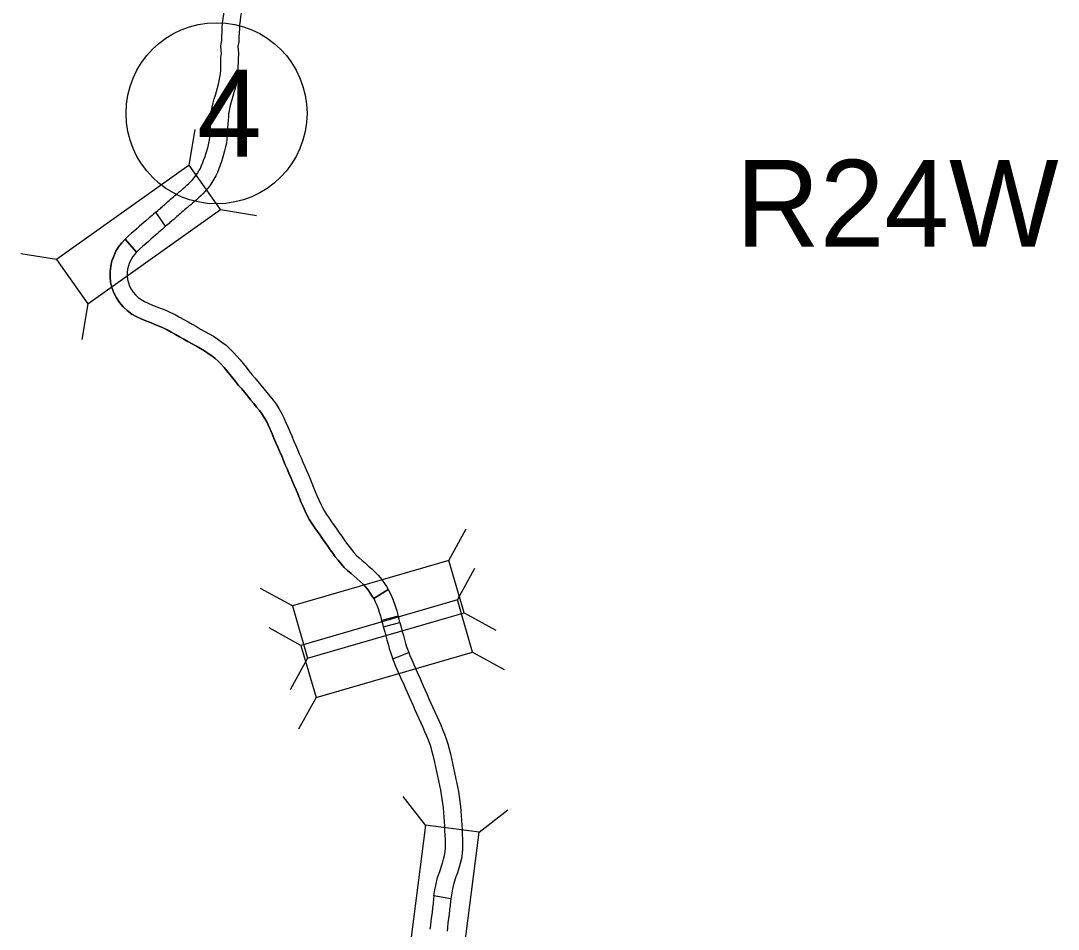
# Model space of a CAD drawing. Extents: x 77230 to 630905, y 790554 to 1662844.
# Drawn here: x 424792 to 439922, y 1490722 to 1503964 of the extents above; entities that cross this region are included whole.
import ezdxf

# ---------------------------------------------------------------- set-up
doc = ezdxf.new("R2010")
doc.units = 0
for name, color, linetype in [('Level 10', 7, 'Continuous'), ('Level 19', 7, 'Continuous'), ('Level 28', 7, 'Continuous'), ('Level 33', 7, 'Continuous')]:
    doc.layers.add(name, color=color, linetype=linetype)

msp = doc.modelspace()

# ---------------------------------------------------------------- linework, layer by layer
at = {"layer": 'Level 10'}
for points in [[(427712, 1503430), (427717, 1503485), (427714, 1503526), (427708, 1503599), (427723, 1503681), (427724, 1503736), (427727, 1503800), (427730, 1503861), (427734, 1503927), (427743, 1503997), (427751, 1504060), (427763, 1504127), (427776, 1504192), (427790, 1504255), (427804, 1504314), (427815, 1504372), (427825, 1504430), (427832, 1504483), (427834, 1504537), (427833, 1504598), (427822, 1504756), (428072, 1504757)], [(428072, 1504757), (428083, 1504600), (428084, 1504533), (428081, 1504461), (428072, 1504393), (428061, 1504328), (428048, 1504262), (428034, 1504199), (428020, 1504139), (428008, 1504081), (427998, 1504023), (427991, 1503966), (427983, 1503904), (427980, 1503849), (427977, 1503788), (427974, 1503726), (427972, 1503656), (427960, 1503588), (427964, 1503546), (427968, 1503483), (427961, 1503408)], [(428072, 1504757), (428083, 1504600), (428084, 1504533), (428081, 1504461), (428072, 1504393), (428061, 1504328), (428048, 1504262), (428034, 1504199), (428020, 1504139), (428008, 1504081), (427998, 1504023), (427991, 1503966), (427983, 1503904), (427980, 1503849), (427977, 1503788), (427974, 1503726), (427972, 1503656), (427960, 1503588), (427964, 1503546), (427968, 1503483), (427961, 1503408)], [(426905, 1500969), (426760, 1501173), (426791, 1501200), (426805, 1501212), (426819, 1501224), (426833, 1501235), (426846, 1501246), (426859, 1501258), (426872, 1501270), (426887, 1501283), (426904, 1501298), (426921, 1501313), (426938, 1501328), (426957, 1501345), (426976, 1501362), (426997, 1501379), (427018, 1501397), (427039, 1501416), (427062, 1501434), (427085, 1501453), (427109, 1501474), (427134, 1501495), (427160, 1501518), (427188, 1501542), (427216, 1501567), (427244, 1501593), (427271, 1501619), (427298, 1501647), (427323, 1501676), (427347, 1501708), (427370, 1501741), (427391, 1501775), (427411, 1501813), (427430, 1501855), (427448, 1501897), (427464, 1501941), (427480, 1501988), (427495, 1502037), (427510, 1502085), (427523, 1502132), (427534, 1502178), (427543, 1502224), (427550, 1502269), (427553, 1502314), (427557, 1502365), (427560, 1502417), (427563, 1502470), (427566, 1502525), (427570, 1502578), (427571, 1502637), (427585, 1502707), (427599, 1502768), (427614, 1502826), (427630, 1502881), (427645, 1502934), (427661, 1502988), (427675, 1503039), (427687, 1503088), (427696, 1503141), (427703, 1503192), (427708, 1503243), (427709, 1503298), (427711, 1503360), (427712, 1503430)], [(427961, 1503408), (427961, 1503354), (427959, 1503291), (427957, 1503229), (427952, 1503163), (427943, 1503102), (427932, 1503038), (427917, 1502976), (427901, 1502919), (427885, 1502865), (427870, 1502812), (427855, 1502761), (427842, 1502709), (427829, 1502654), (427820, 1502610), (427820, 1502567), (427815, 1502509), (427813, 1502456), (427809, 1502402), (427806, 1502349), (427803, 1502295), (427798, 1502240), (427790, 1502182), (427779, 1502125), (427765, 1502069), (427750, 1502015), (427734, 1501962), (427717, 1501911), (427700, 1501858), (427680, 1501805), (427659, 1501753), (427635, 1501703), (427610, 1501653), (427580, 1501605), (427549, 1501559), (427516, 1501517), (427482, 1501479), (427449, 1501444), (427416, 1501411), (427384, 1501382), (427353, 1501354), (427324, 1501329), (427297, 1501305), (427270, 1501283), (427245, 1501262), (427222, 1501243), (427200, 1501224), (427180, 1501207), (427160, 1501190), (427140, 1501173), (427122, 1501157), (427104, 1501141), (427086, 1501126), (427070, 1501111), (427054, 1501097), (427038, 1501082), (427023, 1501069), (427009, 1501057), (426995, 1501046), (426982, 1501034), (426968, 1501022), (426954, 1501010), (426939, 1500997), (426905, 1500969)], [(427961, 1503408), (427961, 1503354), (427959, 1503291), (427957, 1503229), (427952, 1503163), (427943, 1503102), (427932, 1503038), (427917, 1502976), (427901, 1502919), (427885, 1502865), (427870, 1502812), (427855, 1502761), (427842, 1502709), (427829, 1502654), (427820, 1502610), (427820, 1502567), (427815, 1502509), (427813, 1502456), (427809, 1502402), (427806, 1502349), (427803, 1502295), (427798, 1502240), (427790, 1502182), (427779, 1502125), (427765, 1502069), (427750, 1502015), (427734, 1501962), (427717, 1501911), (427700, 1501858), (427680, 1501805), (427659, 1501753), (427635, 1501703), (427610, 1501653), (427580, 1501605), (427549, 1501559), (427516, 1501517), (427482, 1501479), (427449, 1501444), (427416, 1501411), (427384, 1501382), (427353, 1501354), (427324, 1501329), (427297, 1501305), (427270, 1501283), (427245, 1501262), (427222, 1501243), (427200, 1501224), (427180, 1501207), (427160, 1501190), (427140, 1501173), (427122, 1501157), (427104, 1501141), (427086, 1501126), (427070, 1501111), (427054, 1501097), (427038, 1501082), (427023, 1501069), (427009, 1501057), (426995, 1501046), (426982, 1501034), (426968, 1501022), (426954, 1501010), (426939, 1500997), (426905, 1500969)], [(426760, 1501173), (426727, 1501144), (426708, 1501128), (426688, 1501110), (426666, 1501091), (426617, 1501049), (426588, 1501024), (426524, 1500968), (426488, 1500937), (426449, 1500903), (426407, 1500866), (426363, 1500827), (426314, 1500782)], [(426905, 1500969), (426852, 1500922), (426830, 1500902), (426806, 1500881), (426779, 1500859), (426751, 1500835), (426721, 1500809), (426688, 1500780), (426653, 1500749), (426614, 1500714), (426573, 1500679), (426530, 1500641), (426478, 1500593)], [(426478, 1500593), (426314, 1500782), (426265, 1500729), (426219, 1500669), (426180, 1500604), (426147, 1500535), (426122, 1500463), (426104, 1500387), (426095, 1500309), (426094, 1500230), (426103, 1500152), (426121, 1500074), (426149, 1499997), (426187, 1499924), (426232, 1499857), (426286, 1499794), (426345, 1499741), (426410, 1499689), (426483, 1499650), (426550, 1499618), (426617, 1499590), (426683, 1499564), (426749, 1499538)], [(426749, 1499538), (426683, 1499564), (426617, 1499590), (426550, 1499618), (426483, 1499650), (426410, 1499689), (426345, 1499741), (426286, 1499794), (426232, 1499857), (426187, 1499924), (426149, 1499997), (426121, 1500074), (426103, 1500152), (426094, 1500230), (426095, 1500309), (426104, 1500387), (426122, 1500463), (426147, 1500535), (426180, 1500604), (426219, 1500669), (426265, 1500729), (426314, 1500782), (426478, 1500593)], [(426478, 1500593), (426426, 1500528), (426401, 1500486), (426379, 1500440), (426362, 1500392), (426351, 1500343), (426345, 1500294), (426344, 1500244), (426350, 1500194), (426361, 1500144), (426378, 1500097), (426402, 1500052), (426431, 1500009), (426465, 1499969), (426506, 1499932), (426548, 1499899), (426596, 1499873), (426652, 1499846), (426712, 1499821), (426774, 1499796), (426839, 1499772)], [(426478, 1500593), (426426, 1500528), (426401, 1500486), (426379, 1500440), (426362, 1500392), (426351, 1500343), (426345, 1500294), (426344, 1500244), (426350, 1500194), (426361, 1500144), (426378, 1500097), (426402, 1500052), (426431, 1500009), (426465, 1499969), (426506, 1499932), (426548, 1499899), (426596, 1499873), (426652, 1499846), (426712, 1499821), (426774, 1499796), (426839, 1499772)], [(426839, 1499772), (426907, 1499745), (426976, 1499714), (427043, 1499681), (427108, 1499646), (427170, 1499611), (427232, 1499576), (427294, 1499541), (427354, 1499506), (427415, 1499471), (427476, 1499437), (427538, 1499402), (427601, 1499365), (427664, 1499325), (427726, 1499281), (427787, 1499234), (427843, 1499183), (427896, 1499129), (427945, 1499076), (427992, 1499021), (428035, 1498966), (428078, 1498914), (428120, 1498860), (428161, 1498809), (428204, 1498759), (428250, 1498705), (428295, 1498651), (428338, 1498597), (428381, 1498545), (428425, 1498491), (428471, 1498436), (428515, 1498376), (428557, 1498312), (428594, 1498246), (428628, 1498178), (428658, 1498109), (428687, 1498043), (428715, 1497977), (428743, 1497912), (428771, 1497846), (428800, 1497782), (428827, 1497717), (428854, 1497653), (428880, 1497591), (428906, 1497530), (428933, 1497469), (428959, 1497408), (428986, 1497346), (429011, 1497285), (429037, 1497223), (429062, 1497162), (429087, 1497102), (429112, 1497042), (429138, 1496983), (429164, 1496926), (429191, 1496870), (429221, 1496817), (429253, 1496765), (429288, 1496714), (429324, 1496661), (429361, 1496608), (429399, 1496555), (429436, 1496502), (429472, 1496450), (429508, 1496400), (429544, 1496350), (429579, 1496302), (429614, 1496256), (429651, 1496213), (429688, 1496172), (429728, 1496134), (429771, 1496096), (429818, 1496056), (429865, 1496016), (429912, 1495973), (429960, 1495928), (430007, 1495878), (430052, 1495824), (430106, 1495746), (430124, 1495718), (430150, 1495676)], [(426839, 1499772), (426907, 1499745), (426976, 1499714), (427043, 1499681), (427108, 1499646), (427170, 1499611), (427232, 1499576), (427294, 1499541), (427354, 1499506), (427415, 1499471), (427476, 1499437), (427538, 1499402), (427601, 1499365), (427664, 1499325), (427726, 1499281), (427787, 1499234), (427843, 1499183), (427896, 1499129), (427945, 1499076), (427992, 1499021), (428035, 1498966), (428078, 1498914), (428120, 1498860), (428161, 1498809), (428204, 1498759), (428250, 1498705), (428295, 1498651), (428338, 1498597), (428381, 1498545), (428425, 1498491), (428471, 1498436), (428515, 1498376), (428557, 1498312), (428594, 1498246), (428628, 1498178), (428658, 1498109), (428687, 1498043), (428715, 1497977), (428743, 1497912), (428771, 1497846), (428800, 1497782), (428827, 1497717), (428854, 1497653), (428880, 1497591), (428906, 1497530), (428933, 1497469), (428959, 1497408), (428986, 1497346), (429011, 1497285), (429037, 1497223), (429062, 1497162), (429087, 1497102), (429112, 1497042), (429138, 1496983), (429164, 1496926), (429191, 1496870), (429221, 1496817), (429253, 1496765), (429288, 1496714), (429324, 1496661), (429361, 1496608), (429399, 1496555), (429436, 1496502), (429472, 1496450), (429508, 1496400), (429544, 1496350), (429579, 1496302), (429614, 1496256), (429651, 1496213), (429688, 1496172), (429728, 1496134), (429771, 1496096), (429818, 1496056), (429865, 1496016), (429912, 1495973), (429960, 1495928), (430007, 1495878), (430052, 1495824), (430106, 1495746), (430124, 1495718), (430150, 1495676)], [(426749, 1499538), (426810, 1499514), (426870, 1499488), (426928, 1499459), (426987, 1499427), (427048, 1499393), (427108, 1499358), (427169, 1499324), (427230, 1499289), (427292, 1499253), (427353, 1499219), (427413, 1499185), (427471, 1499151), (427526, 1499116), (427577, 1499080), (427625, 1499042), (427671, 1499002), (427714, 1498957), (427757, 1498910), (427799, 1498862), (427840, 1498810), (427883, 1498757), (427925, 1498704), (427969, 1498649), (428014, 1498597), (428059, 1498544), (428101, 1498493), (428144, 1498439), (428189, 1498386), (428232, 1498333), (428273, 1498282), (428310, 1498233), (428343, 1498182), (428374, 1498129), (428402, 1498072), (428429, 1498011), (428456, 1497945), (428485, 1497878), (428514, 1497812), (428542, 1497747), (428570, 1497683), (428597, 1497619), (428624, 1497556), (428650, 1497493), (428677, 1497431), (428703, 1497370), (428730, 1497309), (428755, 1497249), (428781, 1497188), (428806, 1497128), (428831, 1497067), (428857, 1497005), (428882, 1496944), (428909, 1496882), (428938, 1496818), (428970, 1496754), (429005, 1496691), (429042, 1496630), (429081, 1496573), (429119, 1496518), (429157, 1496464), (429194, 1496411), (429231, 1496358), (429268, 1496306), (429305, 1496254), (429342, 1496203), (429379, 1496152), (429420, 1496100), (429463, 1496048), (429509, 1495997), (429559, 1495950), (429608, 1495907), (429655, 1495867), (429700, 1495828), (429744, 1495789), (429784, 1495751), (429820, 1495713), (429852, 1495674), (429897, 1495608), (429913, 1495583), (429940, 1495541), (430150, 1495676)], [(430150, 1495676), (429940, 1495541), (429913, 1495583), (429897, 1495608), (429852, 1495674), (429820, 1495713), (429784, 1495751), (429744, 1495789), (429700, 1495828), (429655, 1495867), (429608, 1495907), (429559, 1495950), (429509, 1495997), (429463, 1496048), (429420, 1496100), (429379, 1496152), (429342, 1496203), (429305, 1496254), (429268, 1496306), (429231, 1496358), (429194, 1496411), (429157, 1496464), (429119, 1496518), (429081, 1496573), (429042, 1496630), (429005, 1496691), (428970, 1496754), (428938, 1496818), (428909, 1496882), (428882, 1496944), (428857, 1497005), (428831, 1497067), (428806, 1497128), (428781, 1497188), (428755, 1497249), (428730, 1497309), (428703, 1497370), (428677, 1497431), (428650, 1497493), (428624, 1497556), (428597, 1497619), (428570, 1497683), (428542, 1497747), (428514, 1497812), (428485, 1497878), (428456, 1497945), (428429, 1498011), (428402, 1498072), (428374, 1498129), (428343, 1498182), (428310, 1498233), (428273, 1498282), (428232, 1498333), (428189, 1498386), (428144, 1498439), (428101, 1498493), (428059, 1498544), (428014, 1498597), (427969, 1498649), (427925, 1498704), (427883, 1498757), (427840, 1498810), (427799, 1498862), (427757, 1498910), (427714, 1498957), (427671, 1499002), (427625, 1499042), (427577, 1499080), (427526, 1499116), (427471, 1499151), (427413, 1499185), (427353, 1499219), (427292, 1499253), (427230, 1499289), (427169, 1499324), (427108, 1499358), (427048, 1499393), (426987, 1499427), (426928, 1499459), (426870, 1499488), (426810, 1499514), (426749, 1499538)], [(430150, 1495676), (430189, 1495600), (430214, 1495541), (430237, 1495482), (430258, 1495421), (430277, 1495361), (430296, 1495287)], [(429940, 1495541), (429961, 1495496), (429983, 1495446), (430003, 1495395), (430020, 1495344), (430036, 1495292), (430055, 1495224)], [(430296, 1495287), (430055, 1495224), (430067, 1495177), (430079, 1495131)], [(430079, 1495131), (430321, 1495195), (430309, 1495241), (430296, 1495287)], [(430321, 1495195), (430340, 1495123), (430356, 1495064), (430372, 1495004), (430388, 1494944), (430405, 1494885), (430424, 1494827), (430449, 1494757)], [(430079, 1495131), (430099, 1495058), (430114, 1494999), (430130, 1494939), (430148, 1494876), (430166, 1494813), (430187, 1494747), (430217, 1494665), (430212, 1494676)], [(430356, 1494345), (430263, 1494551), (430236, 1494616), (430217, 1494665), (430449, 1494757)], [(430449, 1494757), (430468, 1494710), (430493, 1494650), (430588, 1494437)], [(430588, 1494437), (430605, 1494400), (430633, 1494336), (430661, 1494272), (430689, 1494209), (430717, 1494145), (430745, 1494081), (430774, 1494018), (430803, 1493955), (430832, 1493891), (430860, 1493826), (430888, 1493763), (430916, 1493699), (430944, 1493634), (430972, 1493566), (430997, 1493496), (431020, 1493424), (431040, 1493353), (431058, 1493281), (431074, 1493211), (431090, 1493141), (431105, 1493072), (431119, 1493003), (431134, 1492935), (431148, 1492866), (431162, 1492797), (431174, 1492728), (431186, 1492658), (431196, 1492586), (431204, 1492514), (431210, 1492444), (431215, 1492375), (431220, 1492307), (431224, 1492239), (431228, 1492172), (431231, 1492105), (431234, 1492037), (431235, 1491968), (431234, 1491897), (431228, 1491824), (431217, 1491751), (431201, 1491679), (431181, 1491610), (431159, 1491545), (431138, 1491484), (431106, 1491394), (431089, 1491312), (431065, 1491166), (430818, 1491207)], [(430818, 1491207), (430831, 1491294), (430844, 1491361), (430867, 1491474), (430901, 1491563), (430923, 1491626), (430943, 1491685), (430959, 1491741), (430971, 1491796), (430980, 1491852), (430984, 1491909), (430985, 1491968), (430984, 1492030), (430981, 1492094), (430978, 1492159), (430974, 1492224), (430970, 1492290), (430965, 1492357), (430961, 1492424), (430955, 1492490), (430948, 1492555), (430939, 1492620), (430928, 1492685), (430916, 1492751), (430903, 1492817), (430889, 1492883), (430875, 1492951), (430860, 1493019), (430846, 1493087), (430830, 1493155), (430815, 1493222), (430798, 1493288), (430780, 1493353), (430760, 1493416), (430738, 1493477), (430714, 1493537), (430687, 1493599), (430659, 1493662), (430632, 1493726), (430604, 1493788), (430575, 1493851), (430546, 1493915), (430517, 1493979), (430489, 1494043), (430460, 1494107), (430432, 1494172), (430404, 1494236), (430376, 1494299), (430356, 1494345)], [(430818, 1491207), (430812, 1491162), (430805, 1491098), (430797, 1491035), (430790, 1490972), (430782, 1490908), (430774, 1490843), (430766, 1490778), (430759, 1490722)], [(431065, 1491166), (431060, 1491131), (431053, 1491069), (431046, 1491006), (431038, 1490942), (431030, 1490878), (431022, 1490813), (431014, 1490747), (431008, 1490692)]]:
    msp.add_lwpolyline(points, dxfattribs=at)
at = {"layer": 'Level 19'}
for p, q in [((427248, 1501860), (427335, 1502381)), ((427707, 1501215), (428228, 1501128)), ((425313, 1500482), (424792, 1500569)), ((425772, 1499837), (425685, 1499316)), ((431035, 1496097), (431289, 1496559)), ((431160, 1495521), (431414, 1495984)), ((428753, 1495435), (428290, 1495689)), ((431256, 1495336), (431718, 1495082)), ((428878, 1494859), (428415, 1495114)), ((431381, 1494761), (431843, 1494506)), ((428974, 1494674), (428719, 1494212)), ((429099, 1494099), (428844, 1493636)), ((430693, 1492238), (430370, 1492655)), ((431479, 1492137), (431896, 1492460))]:
    msp.add_line(p, q, dxfattribs=at)
for points in [[(425772, 1499837), (427707, 1501215), (427248, 1501860), (425313, 1500482)], [(428974, 1494674), (431256, 1495336), (431035, 1496097), (428753, 1495435)], [(429099, 1494099), (431381, 1494761), (431160, 1495521), (428878, 1494859)], [(430693, 1492238), (430391, 1489881), (431177, 1489780), (431479, 1492137)]]:
    msp.add_lwpolyline(points, close=True, dxfattribs=at)
at = {"layer": 'Level 33'}
msp.add_circle((427647, 1502616), 1320, dxfattribs=at)

# ---------------------------------------------------------------- texts
at = {"layer": 'Level 28'}
msp.add_text('R24W', height=1267.2, dxfattribs=at).set_placement((435220, 1500670))
at = {"layer": 'Level 33'}
msp.add_text('4', height=1267, dxfattribs=at).set_placement((427364, 1501983))

doc.saveas('drawing.dxf')
